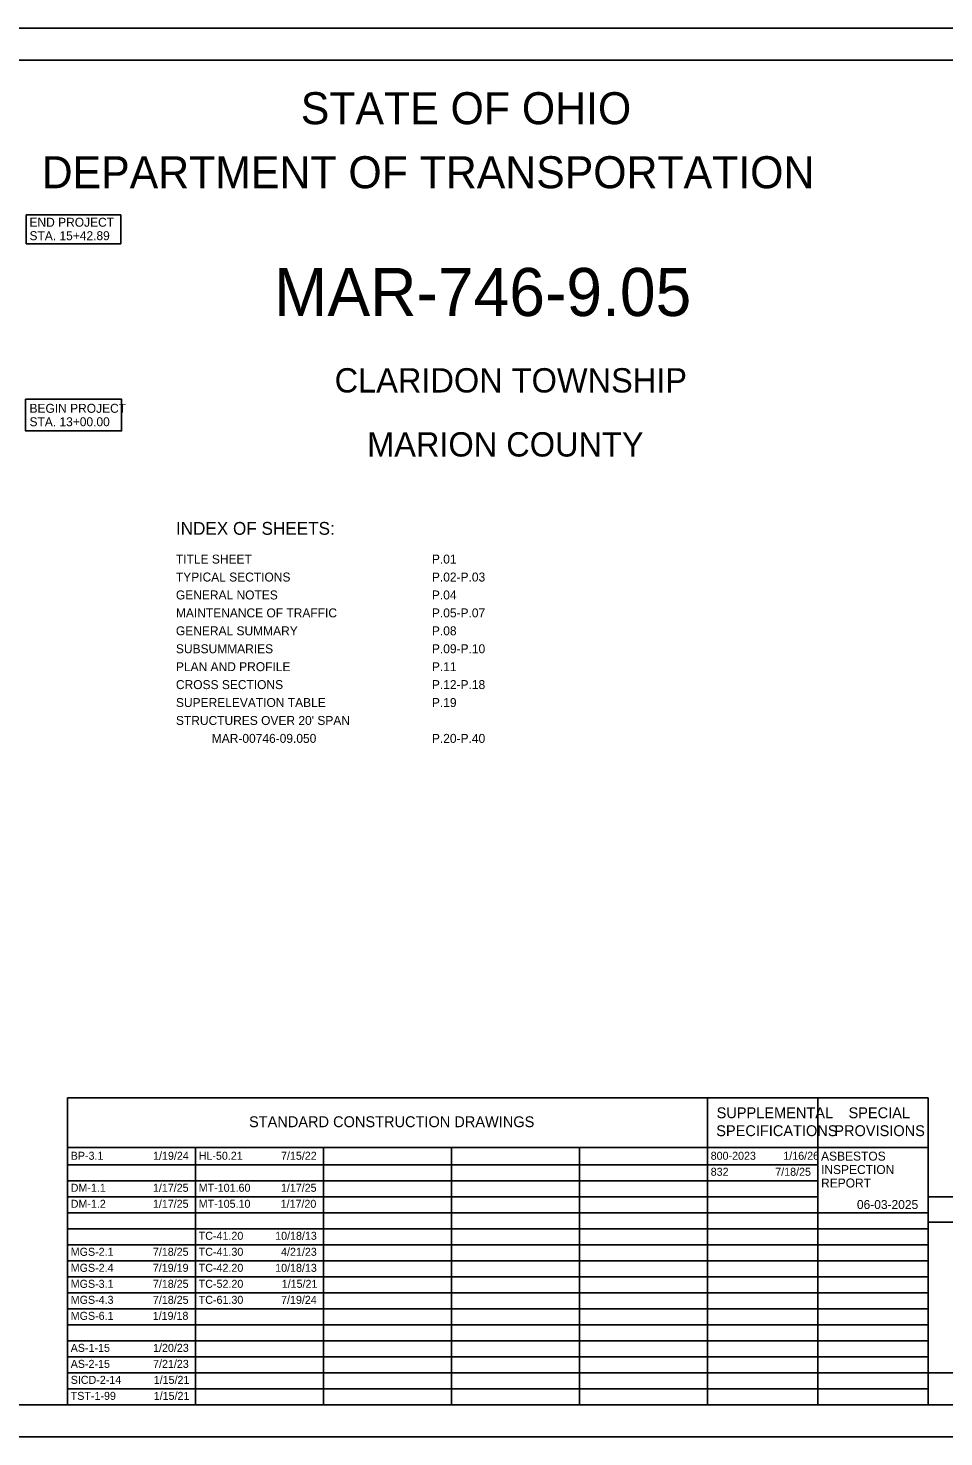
# Model space of a CAD drawing. Extents: x 0 to 45.9, y 0 to 22.
# Drawn here: x 9.53 to 23.84, y 0 to 22 of the extents above; entities that cross this region are included whole.
import ezdxf

# ---------------------------------------------------------------- set-up
doc = ezdxf.new("R2010")
doc.units = 0
for name, color, linetype in [('Default', 7, 'Continuous'), ('SH_Border', 7, 'Continuous'), ('SH_Cut_Line', 7, 'Continuous'), ('SH_Data', 7, 'Continuous'), ('SH_Text', 7, 'Continuous')]:
    doc.layers.add(name, color=color, linetype=linetype)

msp = doc.modelspace()

# ---------------------------------------------------------------- linework, layer by layer
at = {"layer": 'SH_Border'}
for points in [[(9.506, 19.083), (10.983, 19.083), (10.983, 18.632), (9.506, 18.632)], [(9.496, 16.204), (10.995, 16.204), (10.995, 15.71), (9.496, 15.71)]]:
    msp.add_lwpolyline(points, close=True, dxfattribs=at)
at = {"layer": 'SH_Cut_Line'}
for p, q in [((10.15, 5.292), (23.6, 5.292)), ((10.15, 0.5), (10.15, 5.292)), ((20.15, 0.5), (20.15, 5.292)), ((21.875, 0.5), (21.875, 5.292)), ((23.6, 0.5), (23.6, 5.292)), ((10.15, 4.521), (23.6, 4.521)), ((12.15, 0.5), (12.15, 4.521)), ((14.15, 0.5), (14.15, 4.521)), ((16.15, 0.5), (16.15, 4.521)), ((18.15, 0.5), (18.15, 4.521)), ((10.15, 4.25), (21.875, 4.25)), ((10.15, 4), (21.875, 4)), ((10.15, 3.75), (21.875, 3.75)), ((23.6, 0.5), (23.6, 3.75)), ((23.6, 3.75), (26.4, 3.75)), ((10.15, 3.5), (23.6, 3.5)), ((23.6, 3.35), (26.4, 3.35)), ((10.15, 3.25), (23.6, 3.25)), ((10.15, 3), (23.6, 3)), ((10.15, 2.75), (23.6, 2.75)), ((10.15, 2.5), (23.6, 2.5)), ((10.15, 2.25), (23.6, 2.25)), ((10.15, 2), (23.6, 2)), ((10.15, 1.75), (23.6, 1.75)), ((10.15, 1.5), (23.6, 1.5)), ((10.15, 1.25), (23.6, 1.25)), ((10.15, 1), (23.6, 1)), ((10.15, 0.75), (23.6, 0.75)), ((23.6, 0.5), (26.4, 0.5))]:
    msp.add_line(p, q, dxfattribs=at)
msp.add_lwpolyline([(23.6, 0.5), (23.6, 1), (26.4, 1), (26.4, 0.5)], close=True, dxfattribs=at)
at = {"layer": 'SH_Data'}
msp.add_lwpolyline([(1.5, 21.5), (33.5, 21.5), (33.5, 0.5), (1.5, 0.5)], close=True, dxfattribs=at)
at = {"layer": 'SH_Text'}
msp.add_lwpolyline([(0, 0), (34, 0), (34, 22), (0, 22)], close=True, dxfattribs=at)

# ---------------------------------------------------------------- texts
at = {"layer": 'Default'}
for s, height, p in [('BP-3.1', 0.125, (10.2, 4.327)), ('1/19/24', 0.125, (11.487, 4.327)), ('HL-50.21', 0.125, (12.2, 4.327)), ('7/15/22', 0.125, (13.486, 4.327)), ('800-2023', 0.125, (20.2, 4.327)), ('1/16/26', 0.125, (21.335, 4.327)), ('ASBESTOS', 0.14, (21.925, 4.314)), ('832', 0.125, (20.2, 4.077)), ('7/18/25', 0.125, (21.209, 4.077)), ('INSPECTION', 0.14, (21.925, 4.104)), ('REPORT', 0.14, (21.925, 3.894)), ('DM-1.1', 0.125, (10.2, 3.827)), ('1/17/25', 0.125, (11.484, 3.827)), ('MT-101.60', 0.125, (12.2, 3.827)), ('1/17/25', 0.125, (13.484, 3.827)), ('DM-1.2', 0.125, (10.2, 3.577)), ('1/17/25', 0.125, (11.484, 3.577)), ('MT-105.10', 0.125, (12.2, 3.577)), ('1/17/20', 0.125, (13.48, 3.577)), ('06-03-2025', 0.14, (22.485, 3.558)), ('TC-41.20', 0.125, (12.2, 3.077)), ('10/18/13', 0.125, (13.395, 3.077)), ('MGS-2.1', 0.125, (10.2, 2.827)), ('7/18/25', 0.125, (11.484, 2.827)), ('TC-41.30', 0.125, (12.2, 2.827)), ('4/21/23', 0.125, (13.487, 2.827)), ('MGS-2.4', 0.125, (10.2, 2.577)), ('7/19/19', 0.125, (11.483, 2.577)), ('TC-42.20', 0.125, (12.2, 2.577)), ('10/18/13', 0.125, (13.395, 2.577)), ('MGS-3.1', 0.125, (10.2, 2.327)), ('7/18/25', 0.125, (11.484, 2.327)), ('TC-52.20', 0.125, (12.2, 2.327)), ('1/15/21', 0.125, (13.497, 2.327)), ('MGS-4.3', 0.125, (10.2, 2.077)), ('7/18/25', 0.125, (11.484, 2.077)), ('TC-61.30', 0.125, (12.2, 2.077)), ('7/19/24', 0.125, (13.487, 2.077)), ('MGS-6.1', 0.125, (10.2, 1.827)), ('1/19/18', 0.125, (11.481, 1.827)), ('AS-1-15', 0.125, (10.2, 1.327)), ('1/20/23', 0.125, (11.487, 1.327)), ('AS-2-15', 0.125, (10.2, 1.077)), ('7/21/23', 0.125, (11.487, 1.077)), ('SICD-2-14', 0.125, (10.2, 0.827)), ('1/15/21', 0.125, (11.497, 0.827)), ('TST-1-99', 0.125, (10.2, 0.577)), ('1/15/21', 0.125, (11.497, 0.577))]:
    msp.add_text(s, height=height, dxfattribs=at).set_placement(p)
at = {"layer": 'SH_Border'}
for s, height, p in [('STATE OF OHIO', 0.5, (13.795, 20.5)), ('DEPARTMENT OF TRANSPORTATION', 0.5, (9.747, 19.5)), ('END PROJECT', 0.14, (9.556, 18.899)), ('STA. 15+42.89', 0.14, (9.556, 18.689)), ('MAR-746-9.05', 0.75, (13.375, 17.505)), ('CLARIDON TOWNSHIP', 0.38, (14.324, 16.31)), ('BEGIN PROJECT', 0.14, (9.556, 15.993)), ('STA. 13+00.00', 0.14, (9.556, 15.783)), ('MARION COUNTY', 0.38, (14.832, 15.31)), ('INDEX OF SHEETS:', 0.2, (11.844, 14.088)), ('TITLE SHEET', 0.14, (11.844, 13.638)), ('P.01', 0.14, (15.844, 13.638)), ('TYPICAL SECTIONS', 0.14, (11.844, 13.358)), ('P.02-P.03', 0.14, (15.844, 13.358)), ('GENERAL NOTES', 0.14, (11.844, 13.078)), ('P.04', 0.14, (15.844, 13.078)), ('MAINTENANCE OF TRAFFIC', 0.14, (11.844, 12.798)), ('P.05-P.07', 0.14, (15.844, 12.798)), ('GENERAL SUMMARY', 0.14, (11.844, 12.518)), ('P.08', 0.14, (15.844, 12.518)), ('SUBSUMMARIES', 0.14, (11.844, 12.238)), ('P.09-P.10', 0.14, (15.844, 12.238)), ('PLAN AND PROFILE', 0.14, (11.844, 11.958)), ('P.11', 0.14, (15.844, 11.958)), ('CROSS SECTIONS', 0.14, (11.844, 11.678)), ('P.12-P.18', 0.14, (15.844, 11.678)), ('SUPERELEVATION TABLE', 0.14, (11.844, 11.398)), ('P.19', 0.14, (15.844, 11.398)), ("STRUCTURES OVER 20' SPAN", 0.14, (11.844, 11.118)), ('MAR-00746-09.050', 0.14, (12.404, 10.838)), ('P.20-P.40', 0.14, (15.844, 10.838)), ('SUPPLEMENTAL', 0.17, (20.293, 4.976)), ('SPECIAL', 0.17, (22.354, 4.976)), ('STANDARD CONSTRUCTION DRAWINGS', 0.17, (12.986, 4.836)), ('SPECIFICATIONS', 0.17, (20.287, 4.696)), ('PROVISIONS', 0.17, (22.132, 4.696))]:
    msp.add_text(s, height=height, dxfattribs=at).set_placement(p)

doc.saveas('drawing.dxf')
